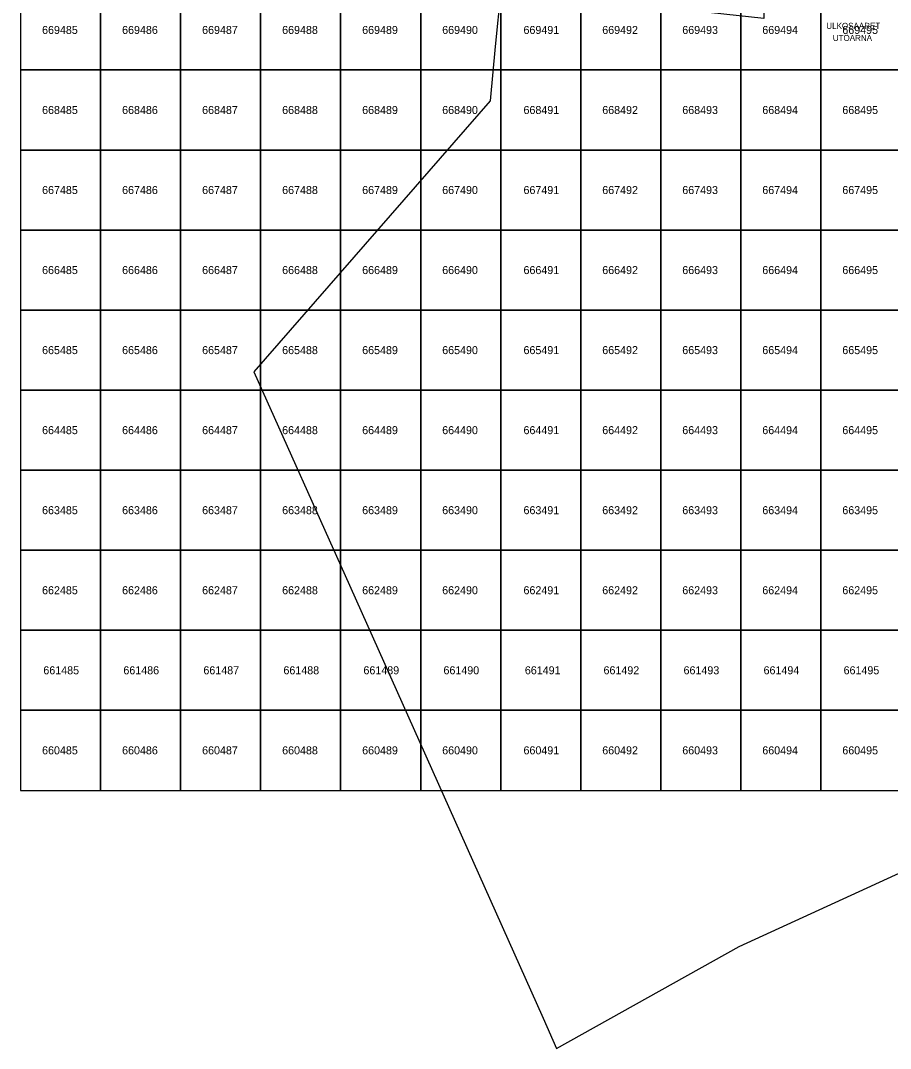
# Model space of a CAD drawing. Extents: x 25485000 to 25520000, y 6656775 to 6690000.
# Drawn here: x 25485000 to 25495870, y 6656775 to 6669617 of the extents above; entities that cross this region are included whole.
import ezdxf

# ---------------------------------------------------------------- set-up
doc = ezdxf.new("R2010")
doc.units = 0
doc.layers.add('Level 63', color=7, linetype='Continuous')

msp = doc.modelspace()

# ---------------------------------------------------------------- linework, layer by layer
at = {"layer": 'Level 63'}
msp.add_lwpolyline([(25506580, 6668434), (25501638, 6667311), (25500576, 6667171), (25499970, 6667780), (25497407, 6670360), (25497357, 6670410), (25496638, 6670410), (25496588, 6670411), (25496587, 6669968), (25495369, 6669969), (25494290, 6669969), (25494289, 6669645), (25492634, 6669823), (25491001, 6669998), (25490933, 6669294), (25490867, 6668614), (25487917, 6665230), (25489109, 6662564), (25491530, 6657153), (25491699, 6656775), (25493980, 6658048), (25507391, 6664195)], dxfattribs=at)
for points in [[(25485000, 6669000), (25486000, 6669000), (25486000, 6670000), (25485000, 6670000)], [(25486000, 6669000), (25487000, 6669000), (25487000, 6670000), (25486000, 6670000)], [(25487000, 6669000), (25488000, 6669000), (25488000, 6670000), (25487000, 6670000)], [(25488000, 6669000), (25489000, 6669000), (25489000, 6670000), (25488000, 6670000)], [(25489000, 6669000), (25490000, 6669000), (25490000, 6670000), (25489000, 6670000)], [(25490000, 6669000), (25491000, 6669000), (25491000, 6670000), (25490000, 6670000)], [(25491000, 6669000), (25492000, 6669000), (25492000, 6670000), (25491000, 6670000)], [(25492000, 6669000), (25493000, 6669000), (25493000, 6670000), (25492000, 6670000)], [(25493000, 6669000), (25494000, 6669000), (25494000, 6670000), (25493000, 6670000)], [(25494000, 6669000), (25495000, 6669000), (25495000, 6670000), (25494000, 6670000)], [(25495000, 6669000), (25496000, 6669000), (25496000, 6670000), (25495000, 6670000)], [(25485000, 6668000), (25486000, 6668000), (25486000, 6669000), (25485000, 6669000)], [(25486000, 6668000), (25487000, 6668000), (25487000, 6669000), (25486000, 6669000)], [(25487000, 6668000), (25488000, 6668000), (25488000, 6669000), (25487000, 6669000)], [(25488000, 6668000), (25489000, 6668000), (25489000, 6669000), (25488000, 6669000)], [(25489000, 6668000), (25490000, 6668000), (25490000, 6669000), (25489000, 6669000)], [(25490000, 6668000), (25491000, 6668000), (25491000, 6669000), (25490000, 6669000)], [(25491000, 6668000), (25492000, 6668000), (25492000, 6669000), (25491000, 6669000)], [(25492000, 6668000), (25493000, 6668000), (25493000, 6669000), (25492000, 6669000)], [(25493000, 6668000), (25494000, 6668000), (25494000, 6669000), (25493000, 6669000)], [(25494000, 6668000), (25495000, 6668000), (25495000, 6669000), (25494000, 6669000)], [(25495000, 6668000), (25496000, 6668000), (25496000, 6669000), (25495000, 6669000)], [(25485000, 6667000), (25486000, 6667000), (25486000, 6668000), (25485000, 6668000)], [(25486000, 6667000), (25487000, 6667000), (25487000, 6668000), (25486000, 6668000)], [(25487000, 6667000), (25488000, 6667000), (25488000, 6668000), (25487000, 6668000)], [(25488000, 6667000), (25489000, 6667000), (25489000, 6668000), (25488000, 6668000)], [(25489000, 6667000), (25490000, 6667000), (25490000, 6668000), (25489000, 6668000)], [(25490000, 6667000), (25491000, 6667000), (25491000, 6668000), (25490000, 6668000)], [(25491000, 6667000), (25492000, 6667000), (25492000, 6668000), (25491000, 6668000)], [(25492000, 6667000), (25493000, 6667000), (25493000, 6668000), (25492000, 6668000)], [(25493000, 6667000), (25494000, 6667000), (25494000, 6668000), (25493000, 6668000)], [(25494000, 6667000), (25495000, 6667000), (25495000, 6668000), (25494000, 6668000)], [(25495000, 6667000), (25496000, 6667000), (25496000, 6668000), (25495000, 6668000)], [(25485000, 6666000), (25486000, 6666000), (25486000, 6667000), (25485000, 6667000)], [(25486000, 6666000), (25487000, 6666000), (25487000, 6667000), (25486000, 6667000)], [(25487000, 6666000), (25488000, 6666000), (25488000, 6667000), (25487000, 6667000)], [(25488000, 6666000), (25489000, 6666000), (25489000, 6667000), (25488000, 6667000)], [(25489000, 6666000), (25490000, 6666000), (25490000, 6667000), (25489000, 6667000)], [(25490000, 6666000), (25491000, 6666000), (25491000, 6667000), (25490000, 6667000)], [(25491000, 6666000), (25492000, 6666000), (25492000, 6667000), (25491000, 6667000)], [(25492000, 6666000), (25493000, 6666000), (25493000, 6667000), (25492000, 6667000)], [(25493000, 6666000), (25494000, 6666000), (25494000, 6667000), (25493000, 6667000)], [(25494000, 6666000), (25495000, 6666000), (25495000, 6667000), (25494000, 6667000)], [(25495000, 6666000), (25496000, 6666000), (25496000, 6667000), (25495000, 6667000)], [(25485000, 6665000), (25486000, 6665000), (25486000, 6666000), (25485000, 6666000)], [(25486000, 6665000), (25487000, 6665000), (25487000, 6666000), (25486000, 6666000)], [(25487000, 6665000), (25488000, 6665000), (25488000, 6666000), (25487000, 6666000)], [(25488000, 6665000), (25489000, 6665000), (25489000, 6666000), (25488000, 6666000)], [(25489000, 6665000), (25490000, 6665000), (25490000, 6666000), (25489000, 6666000)], [(25490000, 6665000), (25491000, 6665000), (25491000, 6666000), (25490000, 6666000)], [(25491000, 6665000), (25492000, 6665000), (25492000, 6666000), (25491000, 6666000)], [(25492000, 6665000), (25493000, 6665000), (25493000, 6666000), (25492000, 6666000)], [(25493000, 6665000), (25494000, 6665000), (25494000, 6666000), (25493000, 6666000)], [(25494000, 6665000), (25495000, 6665000), (25495000, 6666000), (25494000, 6666000)], [(25495000, 6665000), (25496000, 6665000), (25496000, 6666000), (25495000, 6666000)], [(25485000, 6664000), (25486000, 6664000), (25486000, 6665000), (25485000, 6665000)], [(25486000, 6664000), (25487000, 6664000), (25487000, 6665000), (25486000, 6665000)], [(25487000, 6664000), (25488000, 6664000), (25488000, 6665000), (25487000, 6665000)], [(25488000, 6664000), (25489000, 6664000), (25489000, 6665000), (25488000, 6665000)], [(25489000, 6664000), (25490000, 6664000), (25490000, 6665000), (25489000, 6665000)], [(25490000, 6664000), (25491000, 6664000), (25491000, 6665000), (25490000, 6665000)], [(25491000, 6664000), (25492000, 6664000), (25492000, 6665000), (25491000, 6665000)], [(25492000, 6664000), (25493000, 6664000), (25493000, 6665000), (25492000, 6665000)], [(25493000, 6664000), (25494000, 6664000), (25494000, 6665000), (25493000, 6665000)], [(25494000, 6664000), (25495000, 6664000), (25495000, 6665000), (25494000, 6665000)], [(25495000, 6664000), (25496000, 6664000), (25496000, 6665000), (25495000, 6665000)], [(25485000, 6663000), (25486000, 6663000), (25486000, 6664000), (25485000, 6664000)], [(25486000, 6663000), (25487000, 6663000), (25487000, 6664000), (25486000, 6664000)], [(25487000, 6663000), (25488000, 6663000), (25488000, 6664000), (25487000, 6664000)], [(25488000, 6663000), (25489000, 6663000), (25489000, 6664000), (25488000, 6664000)], [(25489000, 6663000), (25490000, 6663000), (25490000, 6664000), (25489000, 6664000)], [(25490000, 6663000), (25491000, 6663000), (25491000, 6664000), (25490000, 6664000)], [(25491000, 6663000), (25492000, 6663000), (25492000, 6664000), (25491000, 6664000)], [(25492000, 6663000), (25493000, 6663000), (25493000, 6664000), (25492000, 6664000)], [(25493000, 6663000), (25494000, 6663000), (25494000, 6664000), (25493000, 6664000)], [(25494000, 6663000), (25495000, 6663000), (25495000, 6664000), (25494000, 6664000)], [(25495000, 6663000), (25496000, 6663000), (25496000, 6664000), (25495000, 6664000)], [(25485000, 6662000), (25486000, 6662000), (25486000, 6663000), (25485000, 6663000)], [(25486000, 6662000), (25487000, 6662000), (25487000, 6663000), (25486000, 6663000)], [(25487000, 6662000), (25488000, 6662000), (25488000, 6663000), (25487000, 6663000)], [(25488000, 6662000), (25489000, 6662000), (25489000, 6663000), (25488000, 6663000)], [(25489000, 6662000), (25490000, 6662000), (25490000, 6663000), (25489000, 6663000)], [(25490000, 6662000), (25491000, 6662000), (25491000, 6663000), (25490000, 6663000)], [(25491000, 6662000), (25492000, 6662000), (25492000, 6663000), (25491000, 6663000)], [(25492000, 6662000), (25493000, 6662000), (25493000, 6663000), (25492000, 6663000)], [(25493000, 6662000), (25494000, 6662000), (25494000, 6663000), (25493000, 6663000)], [(25494000, 6662000), (25495000, 6662000), (25495000, 6663000), (25494000, 6663000)], [(25495000, 6662000), (25496000, 6662000), (25496000, 6663000), (25495000, 6663000)], [(25485000, 6661000), (25486000, 6661000), (25486000, 6662000), (25485000, 6662000)], [(25486000, 6661000), (25487000, 6661000), (25487000, 6662000), (25486000, 6662000)], [(25487000, 6661000), (25488000, 6661000), (25488000, 6662000), (25487000, 6662000)], [(25488000, 6661000), (25489000, 6661000), (25489000, 6662000), (25488000, 6662000)], [(25489000, 6661000), (25490000, 6661000), (25490000, 6662000), (25489000, 6662000)], [(25490000, 6661000), (25491000, 6661000), (25491000, 6662000), (25490000, 6662000)], [(25491000, 6661000), (25492000, 6661000), (25492000, 6662000), (25491000, 6662000)], [(25492000, 6661000), (25493000, 6661000), (25493000, 6662000), (25492000, 6662000)], [(25493000, 6661000), (25494000, 6661000), (25494000, 6662000), (25493000, 6662000)], [(25494000, 6661000), (25495000, 6661000), (25495000, 6662000), (25494000, 6662000)], [(25495000, 6661000), (25496000, 6661000), (25496000, 6662000), (25495000, 6662000)], [(25485000, 6660000), (25486000, 6660000), (25486000, 6661000), (25485000, 6661000)], [(25486000, 6660000), (25487000, 6660000), (25487000, 6661000), (25486000, 6661000)], [(25487000, 6660000), (25488000, 6660000), (25488000, 6661000), (25487000, 6661000)], [(25488000, 6660000), (25489000, 6660000), (25489000, 6661000), (25488000, 6661000)], [(25489000, 6660000), (25490000, 6660000), (25490000, 6661000), (25489000, 6661000)], [(25490000, 6660000), (25491000, 6660000), (25491000, 6661000), (25490000, 6661000)], [(25491000, 6660000), (25492000, 6660000), (25492000, 6661000), (25491000, 6661000)], [(25492000, 6660000), (25493000, 6660000), (25493000, 6661000), (25492000, 6661000)], [(25493000, 6660000), (25494000, 6660000), (25494000, 6661000), (25493000, 6661000)], [(25494000, 6660000), (25495000, 6660000), (25495000, 6661000), (25494000, 6661000)], [(25495000, 6660000), (25496000, 6660000), (25496000, 6661000), (25495000, 6661000)]]:
    msp.add_lwpolyline(points, close=True, dxfattribs=at)

# ---------------------------------------------------------------- texts
for s, height, p in [('ULKOSAARET', 75, (25495069, 6669514)), ('669485', 100, (25485269, 6669450)), ('669486', 100, (25486269, 6669450)), ('669487', 100, (25487269, 6669450)), ('669488', 100, (25488269, 6669450)), ('669489', 100, (25489269, 6669450)), ('669490', 100, (25490269, 6669450)), ('669491', 100, (25491285, 6669450)), ('669492', 100, (25492269, 6669450)), ('669493', 100, (25493269, 6669450)), ('669494', 100, (25494269, 6669450)), ('669495', 100, (25495269, 6669450)), ('UTÖARNA', 75, (25495150, 6669363)), ('668485', 100, (25485269, 6668450)), ('668486', 100, (25486269, 6668450)), ('668487', 100, (25487269, 6668450)), ('668488', 100, (25488269, 6668450)), ('668489', 100, (25489269, 6668450)), ('668490', 100, (25490269, 6668450)), ('668491', 100, (25491285, 6668450)), ('668492', 100, (25492269, 6668450)), ('668493', 100, (25493269, 6668450)), ('668494', 100, (25494269, 6668450)), ('668495', 100, (25495269, 6668450)), ('667485', 100, (25485269, 6667450)), ('667486', 100, (25486269, 6667450)), ('667487', 100, (25487269, 6667450)), ('667488', 100, (25488269, 6667450)), ('667489', 100, (25489269, 6667450)), ('667490', 100, (25490269, 6667450)), ('667491', 100, (25491285, 6667450)), ('667492', 100, (25492269, 6667450)), ('667493', 100, (25493269, 6667450)), ('667494', 100, (25494269, 6667450)), ('667495', 100, (25495269, 6667450)), ('666485', 100, (25485269, 6666450)), ('666486', 100, (25486269, 6666450)), ('666487', 100, (25487269, 6666450)), ('666488', 100, (25488269, 6666450)), ('666489', 100, (25489269, 6666450)), ('666490', 100, (25490269, 6666450)), ('666491', 100, (25491285, 6666450)), ('666492', 100, (25492269, 6666450)), ('666493', 100, (25493269, 6666450)), ('666494', 100, (25494269, 6666450)), ('666495', 100, (25495269, 6666450)), ('665485', 100, (25485269, 6665450)), ('665486', 100, (25486269, 6665450)), ('665487', 100, (25487269, 6665450)), ('665488', 100, (25488269, 6665450)), ('665489', 100, (25489269, 6665450)), ('665490', 100, (25490269, 6665450)), ('665491', 100, (25491285, 6665450)), ('665492', 100, (25492269, 6665450)), ('665493', 100, (25493269, 6665450)), ('665494', 100, (25494269, 6665450)), ('665495', 100, (25495269, 6665450)), ('664485', 100, (25485269, 6664450)), ('664486', 100, (25486269, 6664450)), ('664487', 100, (25487269, 6664450)), ('664488', 100, (25488269, 6664450)), ('664489', 100, (25489269, 6664450)), ('664490', 100, (25490269, 6664450)), ('664491', 100, (25491285, 6664450)), ('664492', 100, (25492269, 6664450)), ('664493', 100, (25493269, 6664450)), ('664494', 100, (25494269, 6664450)), ('664495', 100, (25495269, 6664450)), ('663485', 100, (25485269, 6663450)), ('663486', 100, (25486269, 6663450)), ('663487', 100, (25487269, 6663450)), ('663488', 100, (25488269, 6663450)), ('663489', 100, (25489269, 6663450)), ('663490', 100, (25490269, 6663450)), ('663491', 100, (25491285, 6663450)), ('663492', 100, (25492269, 6663450)), ('663493', 100, (25493269, 6663450)), ('663494', 100, (25494269, 6663450)), ('663495', 100, (25495269, 6663450)), ('662485', 100, (25485269, 6662450)), ('662486', 100, (25486269, 6662450)), ('662487', 100, (25487269, 6662450)), ('662488', 100, (25488269, 6662450)), ('662489', 100, (25489269, 6662450)), ('662490', 100, (25490269, 6662450)), ('662491', 100, (25491285, 6662450)), ('662492', 100, (25492269, 6662450)), ('662493', 100, (25493269, 6662450)), ('662494', 100, (25494269, 6662450)), ('662495', 100, (25495269, 6662450)), ('661485', 100, (25485285, 6661450)), ('661486', 100, (25486285, 6661450)), ('661487', 100, (25487285, 6661450)), ('661488', 100, (25488285, 6661450)), ('661489', 100, (25489285, 6661450)), ('661490', 100, (25490285, 6661450)), ('661491', 100, (25491302, 6661450)), ('661492', 100, (25492285, 6661450)), ('661493', 100, (25493285, 6661450)), ('661494', 100, (25494285, 6661450)), ('661495', 100, (25495285, 6661450)), ('660485', 100, (25485269, 6660450)), ('660486', 100, (25486269, 6660450)), ('660487', 100, (25487269, 6660450)), ('660488', 100, (25488269, 6660450)), ('660489', 100, (25489269, 6660450)), ('660490', 100, (25490269, 6660450)), ('660491', 100, (25491285, 6660450)), ('660492', 100, (25492269, 6660450)), ('660493', 100, (25493269, 6660450)), ('660494', 100, (25494269, 6660450)), ('660495', 100, (25495269, 6660450))]:
    msp.add_text(s, height=height, dxfattribs=at).set_placement(p)

doc.saveas('drawing.dxf')
